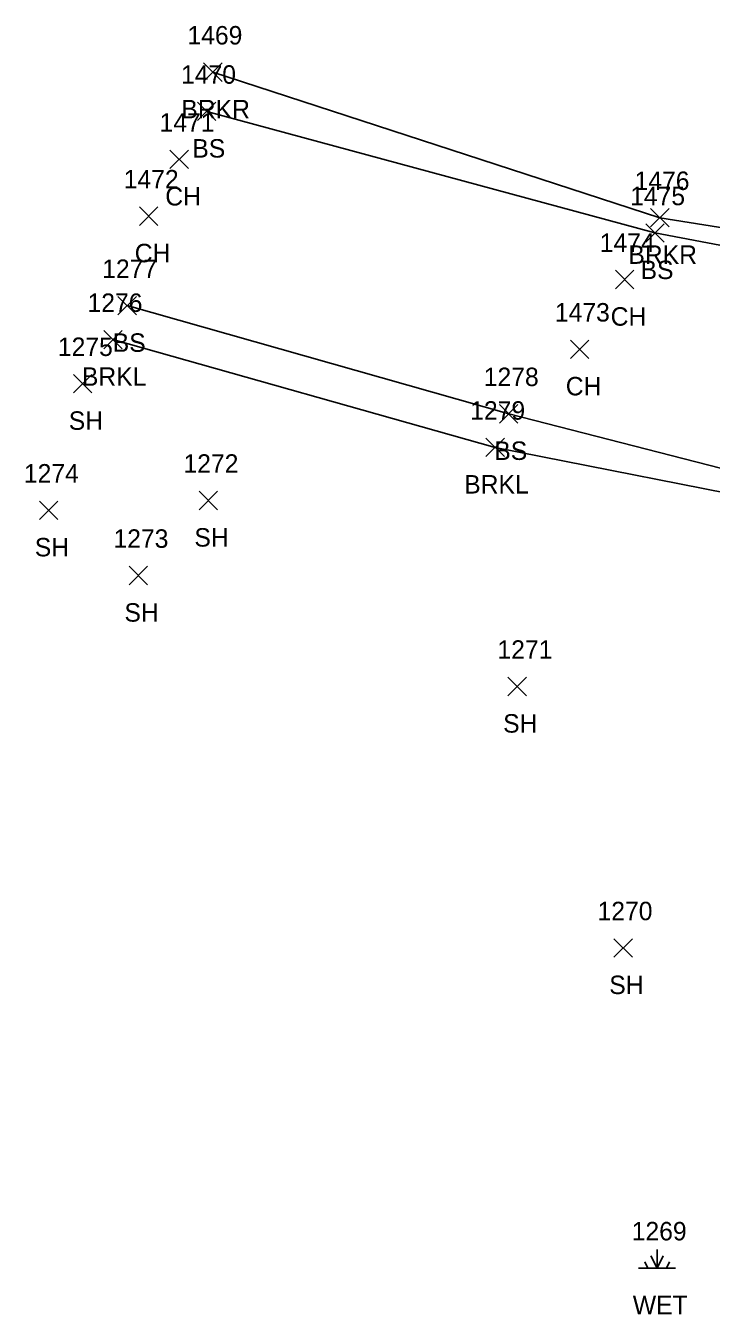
# Model space of a CAD drawing. Extents: x 1654425 to 1656893, y 667839 to 678429.
# Drawn here: x 1654425.4 to 1654499.7, y 668287 to 668426.5 of the extents above; entities that cross this region are included whole.
import ezdxf

# ---------------------------------------------------------------- set-up
doc = ezdxf.new("R2010")
doc.units = 0
for name, color, linetype in [('L_A', 7, 'Continuous'), ('L_I', 7, 'Continuous'), ('L_TIC', 7, 'Continuous'), ('LAWE', 7, 'Continuous'), ('LELB', 7, 'Continuous'), ('LWET', 7, 'Continuous')]:
    doc.layers.add(name, color=color, linetype=linetype)

msp = doc.modelspace()

# ---------------------------------------------------------------- linework, layer by layer
at = {"layer": 'L_TIC'}
for points in [[(1654444.7, 668420.51), (1654446.7, 668422.51)], [(1654446.7, 668420.51), (1654444.7, 668422.51)], [(1654444.04, 668416.26), (1654446.04, 668418.26)], [(1654446.04, 668416.26), (1654444.04, 668418.26)], [(1654441.06, 668411.07), (1654443.06, 668413.07)], [(1654443.06, 668411.07), (1654441.06, 668413.07)], [(1654437.75, 668404.92), (1654439.75, 668406.92)], [(1654439.75, 668404.92), (1654437.75, 668406.92)], [(1654493.11, 668404.75), (1654495.11, 668406.75)], [(1654495.11, 668404.75), (1654493.11, 668406.75)], [(1654492.58, 668403.1), (1654494.58, 668405.1)], [(1654494.58, 668403.1), (1654492.58, 668405.1)], [(1654489.29, 668398.05), (1654491.29, 668400.05)], [(1654491.29, 668398.05), (1654489.29, 668400.05)], [(1654435.42, 668395.22), (1654437.42, 668397.22)], [(1654437.42, 668395.22), (1654435.42, 668397.22)], [(1654433.88, 668391.54), (1654435.88, 668393.54)], [(1654435.88, 668391.54), (1654433.88, 668393.54)], [(1654484.43, 668390.5), (1654486.43, 668392.5)], [(1654486.43, 668390.5), (1654484.43, 668392.5)], [(1654430.61, 668386.77), (1654432.61, 668388.77)], [(1654432.61, 668386.77), (1654430.61, 668388.77)], [(1654476.74, 668383.51), (1654478.74, 668385.51)], [(1654478.74, 668383.51), (1654476.74, 668385.51)], [(1654475.27, 668379.87), (1654477.27, 668381.87)], [(1654477.27, 668379.87), (1654475.27, 668381.87)], [(1654444.22, 668374.12), (1654446.22, 668376.12)], [(1654446.22, 668374.12), (1654444.22, 668376.12)], [(1654426.93, 668373.06), (1654428.93, 668375.06)], [(1654428.93, 668373.06), (1654426.93, 668375.06)], [(1654436.64, 668365.99), (1654438.64, 668367.99)], [(1654438.64, 668365.99), (1654436.64, 668367.99)], [(1654477.65, 668353.97), (1654479.65, 668355.97)], [(1654479.65, 668353.97), (1654477.65, 668355.97)], [(1654489.14, 668325.65), (1654491.14, 668327.65)], [(1654491.14, 668325.65), (1654489.14, 668327.65)]]:
    msp.add_lwpolyline(points, dxfattribs=at)
at = {"layer": 'LAWE'}
for points in [[(1654445.7, 668421.51), (1654494.11, 668405.75), (1654530.62, 668399.91), (1654558.13, 668391.51)], [(1654434.88, 668392.54), (1654476.27, 668380.87), (1654508.86, 668374.43), (1654533.02, 668367.65)]]:
    msp.add_lwpolyline(points, dxfattribs=at)
at = {"layer": 'LELB'}
for points in [[(1654445.04, 668417.26), (1654493.58, 668404.1), (1654529.11, 668397.34), (1654556.9, 668389.59)], [(1654436.42, 668396.22), (1654477.74, 668384.51), (1654510.24, 668376.15), (1654535.4, 668369.35)]]:
    msp.add_lwpolyline(points, dxfattribs=at)
at = {"layer": 'LWET'}
for p, q in [((1654493.81, 668291.97), (1654493.81, 668293.97)), ((1654492.81, 668291.97), (1654492.47, 668292.64)), ((1654493.81, 668291.97), (1654493.14, 668293.31)), ((1654493.81, 668291.97), (1654494.47, 668293.31)), ((1654494.81, 668291.97), (1654495.14, 668292.64)), ((1654495.81, 668291.97), (1654491.81, 668291.97))]:
    msp.add_line(p, q, dxfattribs=at)

# ---------------------------------------------------------------- texts
at = {"layer": 'L_A'}
for s, p in [('BRKR', (1654442.29, 668416.51)), ('BS', (1654443.48, 668412.26)), ('CH', (1654440.55, 668407.07)), ('CH', (1654437.24, 668400.92)), ('BRKR', (1654490.7, 668400.75)), ('BS', (1654492.02, 668399.1)), ('CH', (1654488.78, 668394.05)), ('BS', (1654434.86, 668391.22)), ('BRKL', (1654431.52, 668387.54)), ('CH', (1654483.92, 668386.5)), ('SH', (1654430.1, 668382.77)), ('BS', (1654476.18, 668379.51)), ('BRKL', (1654472.92, 668375.87)), ('SH', (1654443.7, 668370.12)), ('SH', (1654426.42, 668369.06)), ('SH', (1654436.13, 668361.99)), ('SH', (1654477.14, 668349.97)), ('SH', (1654488.63, 668321.65)), ('WET', (1654491.18, 668286.97))]:
    msp.add_text(s, height=2, dxfattribs=at).set_placement(p)
at = {"layer": 'L_I'}
for s, p in [('1469', (1654442.95, 668424.51)), ('1470', (1654442.26, 668420.26)), ('1471', (1654439.93, 668415.07)), ('1472', (1654436.05, 668408.92)), ('1476', (1654491.37, 668408.75)), ('1475', (1654490.89, 668407.1)), ('1474', (1654487.6, 668402.05)), ('1277', (1654433.72, 668399.22)), ('1276', (1654432.13, 668395.54)), ('1473', (1654482.74, 668394.5)), ('1275', (1654428.92, 668390.77)), ('1278', (1654475.04, 668387.51)), ('1279', (1654473.57, 668383.87)), ('1272', (1654442.52, 668378.12)), ('1274', (1654425.24, 668377.06)), ('1273', (1654434.94, 668369.99)), ('1271', (1654476.52, 668357.97)), ('1270', (1654487.36, 668329.65)), ('1269', (1654491.06, 668294.97))]:
    msp.add_text(s, height=2, dxfattribs=at).set_placement(p)

doc.saveas('drawing.dxf')
